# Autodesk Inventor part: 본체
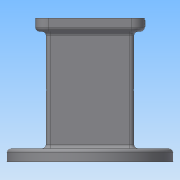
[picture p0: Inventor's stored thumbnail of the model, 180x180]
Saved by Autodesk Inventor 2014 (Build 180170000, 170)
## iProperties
Created: 2018-10
Part Number: 본체
Material: Generic
Document SubType Name: Modeling
Designer: Administrator
Density: 1 g/cm^3
Appearance: Default
Author: Administrator
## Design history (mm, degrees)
sketch "스케치1"
  geometry: L1 (-37, 33)-(37, 33); L2 (37, 33)-(37, -33); L3 (37, -33)-(-37, -33); L4 (-37, -33)-(-37, 33); 1 further point
  constraints: 8 end point, 2 parallel, 1 horizontal, 1 perpendicular
  dimensions: "d0" = 74 distance of L1.start L1.end; "d1" = 66 distance of L1.end L2.end; "d2" = 33 distance from line of point (0, 0) L1; "d3" = 37 distance from line of point (0, 0) L4
extrude "돌출1" new body sketch "스케치1" stored distance "d4" = 108; taper "d5" = 0 deg
sketch "스케치2"
  geometry: L1 (-37, -33)-(37, -33) reference; L2 (37, -33)-(37, 33) reference; L3 (37, 33)-(-37, 33) reference; L4 (-37, 33)-(-37, -33) reference; L5 (-46, 41)-(46, 41); L6 (46, 41)-(46, -41); L7 (46, -41)-(-46, -41); L8 (-46, -41)-(-46, 41); 1 further point
  constraints: 8 end point, 2 parallel, 1 horizontal, 1 perpendicular
  dimensions: "d6" = 92 distance of L5.start L5.end; "d7" = 82 distance of L5.end L6.end; "d8" = 41 distance from line of point (0, 0) L5; "d9" = 46 distance from line of point (0, 0) L8
extrude "돌출2" join sketch "스케치2" distance "d10" = 10; taper "d11" = 0 deg
sketch "스케치3"
  geometry: L1 (37, 33)-(-37, 33) reference; L2 (-37, 33)-(-37, -33) reference; L3 (-37, -33)-(37, -33) reference; L4 (37, -33)-(37, 33) reference; C1 r 62.5 at (0, 0); 1 further point
  constraints: 1 centre point, 1 coincident
  dimensions: "d12" = 125 diameter of C1
extrude "돌출3" join sketch "스케치3" distance "d13" = 10; taper "d14" = 0 deg
sketch "스케치4" dims "d15" = 100
  geometry: C1 r 62.5 at (0, 0) reference; 2 further points
  constraints: 1 coincident, 1 horizontal alignment, 2 other
  dimensions: "d16" = 0 vertical distance of C1.centre point (-50, 0)
hole "구멍1" sketch "스케치4" at (-50, 0) diameter "d17" = 9; stored, may be unused: countersink angle "d21" = 90 deg, drill point angle "d23" = 118 deg; dims "d18" = 6, "d19" = 4, "d20" = 2, "d22" = 10
sketch "스케치5"
  geometry: L1 (62.5, -54)-(-62.5, -54) reference; L2 (0, -54)-(0, 0); L3 (-28, -54)-(-24.826, -36); L4 (-24.826, -36)-(0, -36); L5 (-28, -54)-(0, -54)
  constraints: 8 end point, 3 perpendicular, 2 point on line, 1 midpoint
  dimensions: "d27" = 56 diameter of L3.start L2; "d28" = 18 distance between parallel lines of L1 L4; "d29" = 80 deg angle of L1 L3
revolve "회전1" sketch "스케치5" stored, may be unused: angle "d30" = 90 deg
sketch "스케치7"
  geometry: L1 (99.5, -98)-(-25.5, -98) reference; C1 r 35 at (37, -44); 1 further point
  constraints: 1 centre point
  dimensions: "d33" = 70 diameter of C1; "d34" = 54 distance from line of L1 C1.centre; "d35" = 0 distance of point (37, -44) C1.centre
extrude "돌출4" cut sketch "스케치7" distance "d36" = 3; taper "d37" = 0 deg
sketch "스케치8"
  geometry: C1 r 35 at (0, 0) reference; C2 r 24 at (0, 0)
  constraints: 1 centre point, 1 coincident
  dimensions: "d38" = 48 diameter of C2
extrude "돌출5" cut sketch "스케치8" stored distance "d39" = 3; taper "d40" = 0 deg
sketch "스케치9"
  geometry: L1 (-26, 26)-(26, 26); L2 (26, 26)-(26, -26); L3 (26, -26)-(-26, -26); L4 (-26, -26)-(-26, 26); 1 further point
  constraints: 8 end point, 2 parallel, 1 horizontal, 1 perpendicular
  dimensions: "d41" = 52 distance of L1.start L1.end; "d42" = 52 distance of L1.end L2.end; "d43" = 26 distance from line of point (0, 0) L1; "d44" = 26 distance from line of point (0, 0) L4
extrude "돌출6" cut sketch "스케치9" distance "d45" = 8; taper "d46" = 0 deg
sketch "스케치10"
  geometry: L1 (-22, 22)-(22, 22); L2 (22, 22)-(22, -22); L3 (22, -22)-(-22, -22); L4 (-22, -22)-(-22, 22); 1 further point
  constraints: 8 end point, 2 parallel, 1 horizontal, 1 perpendicular
  dimensions: "d47" = 44 distance of L1.start L1.end; "d48" = 44 distance of L1.end L2.end; "d49" = 22 distance from line of point (0, 0) L1; "d50" = 22 distance from line of point (0, 0) L4
extrude "돌출7" cut sketch "스케치10" distance "d51" = 82; taper "d52" = 0 deg
sketch "스케치11"
  geometry: L1 (95.5, -98)-(-29.5, -98) reference; 3 further points
  dimensions: "d54" = 37 distance from line of L1 point (33, -61); "d55" = 43 distance of point (33, -61) point (33, -18); "d56" = 0 horizontal distance of point (33, -44) point (33, -18); "d57" = 0 horizontal distance of point (33, -44) point (33, -61)
hole "구멍2" sketch "스케치11" at (33, -18), (33, -61) diameter "d58" = 4.134; stored, may be unused: countersink angle "d62" = 90 deg, drill point angle "d64" = 118 deg; dims "d59" = 6, "d60" = 4, "d61" = 2, "d63" = 30
sketch "스케치12"
  geometry: C1 r 24 at (0, 0) reference; 1 further point
  dimensions: "d65" = 29 distance of C1.centre point (0, 29); "d66" = 0 horizontal distance of C1.centre point (0, 29)
hole "구멍3" sketch "스케치12" at (0, 29) diameter "d67" = 3.242; stored, may be unused: countersink angle "d71" = 82 deg, drill point angle "d73" = 0 deg; dims "d68" = 4, "d69" = 3.023, "d70" = 2, "d72" = 6
fillet "모깎기1" dims "d77" = 10
sketch "스케치13"
  geometry: A1 r 10 centre (-36, 31) between (-36, 41) and (-46, 31) reference; A2 r 10 centre (-36, -31) between (-46, -31) and (-36, -41) reference; A3 r 10 centre (36, -31) between (36, -41) and (46, -31) reference; A4 r 10 centre (36, 31) between (46, 31) and (36, 41) reference; 5 further points
  constraints: 4 coincident
hole "구멍4" sketch "스케치13" at (-36, 31), (36, 31), (-36, -31), (36, -31) diameter "d78" = 3.242; stored, may be unused: countersink angle "d82" = 82 deg, drill point angle "d84" = 0 deg; dims "d79" = 4, "d80" = 3.023, "d81" = 2, "d83" = 6
fillet "모깎기2" dims "d85" = 3
fillet "모깎기3" dims "d86" = 3
fillet "모깎기4" dims "d87" = 3
fillet "모깎기5" dims "d88" = 3
fillet "모깎기6" dims "d89" = 3
fillet "모깎기7" dims "d90" = 3
fillet "모깎기8" dims "d91" = 3
chamfer "모따기1" distance "d92" = 1; stored, may be unused: second distance "d93" = 2, angle "d94" = 45 deg
fillet "모깎기9" dims "d95" = 3
sketch "스케치14"
  geometry: L1 (72, 0)-(0, 0) reference; L2 (-10, 0)-(-10, -7) reference; 2 further points
  constraints: 1 other
  dimensions: "d96" = 4 distance from line of L1 point (36, -4); "d97" = 46 distance from line of point (36, -4) L2
feature "엠보싱1" sketch "스케치14" dims "d0" = 74, "d1" = 66, "d2" = 33, "d3" = 37, "d98" = 0.5, "d99" = 0
node "솔리드1"
pattern_circular "원형 패턴1" dims angle "d25" = 360 deg
mirror "대칭1"
pattern_circular "원형 패턴2" dims angle "d75" = 360 deg
mirror "대칭2"
